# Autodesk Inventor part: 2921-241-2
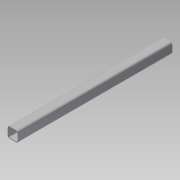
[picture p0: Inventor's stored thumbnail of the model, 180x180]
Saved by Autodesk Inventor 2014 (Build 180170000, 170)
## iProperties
Company: NHTSA/VRTC
Created: 2011-11
Part Number: 2921-241-2
Material: Steel
Document SubType Name: Modeling
Designer: Dave Walker
Density: 7.85 g/cm^3
Project: CHILD SIDE IMPACT SLED
Description: T.S. 2" x 2" x 1/8" x 749.3mm (29.50")
Mass: 3299.09 g
Surface Area: 2658.57 cm^2
Volume: 420.267 cm^3
Stock Number: IMPACTOR FRAME TUBE 2
Appearance: Steel
Author: Dave Walker
Title: Impactor Frame Tube 2
Subject: Child Side Impact Sled
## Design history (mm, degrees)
node "Sketch1"
node "2921-105-21"
node "2921-105-2"
node "Base1"
